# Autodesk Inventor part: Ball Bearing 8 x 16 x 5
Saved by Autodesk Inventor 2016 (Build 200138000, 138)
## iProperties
Created: 2016-01
Part Number: Ball Bearing 8 x 16 x 5
Material: Generic
Document SubType Name: Modeling
Designer: John
Density: 1 g/cm^3
Appearance: Default
Author: John
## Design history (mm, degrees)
feature "REVOLVE1"
body "Solid1"
